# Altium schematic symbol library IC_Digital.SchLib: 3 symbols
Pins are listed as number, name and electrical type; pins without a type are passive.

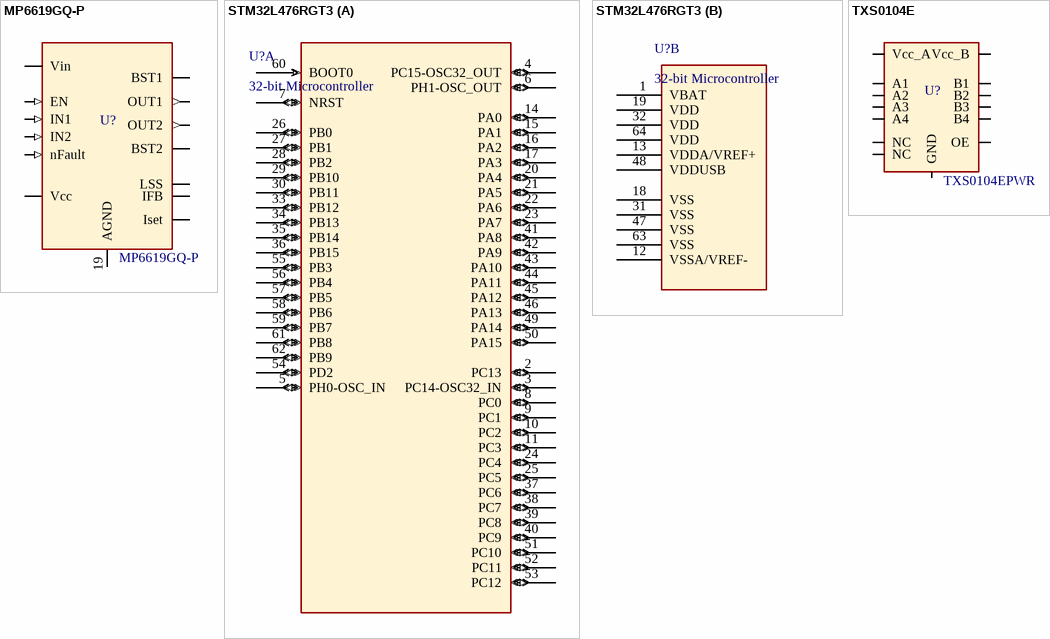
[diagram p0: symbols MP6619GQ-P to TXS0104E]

## MP6619GQ-P
designator U?  Mfr Part Num: MP6619GQ-P  (hidden comment: *)
H-Bridge Motor driver; Manufacturer: MPS; Supply Voltage: 5.4V~28V; Output Current: 5A
footprint MP6619GQ-P (19-pin, QFN-19_3x3mm)
pins: 1 IFB, 2 Vin (power), 3 OUT2 (out), 4 BST2, 5 EN (in), 6 LSS, 7 LSS, 8 LSS, 9 BST1, 10 OUT1 (out), 11 Vin (power), 13 nFault (in), 14 Vcc (power), 15 IN1 (in), 16 IN2 (in), 17 Iset, 19 AGND

## STM32L476RGT3
designator U?, comment 32-bit Microcontroller
STM32 Arm-based 32-bit Microcontroller; Mfr Part Num: STM32L476RGT3; Manufacturer: STMicroelectronics; Supply Voltage: 1.7V~3.6V; RAM Memory Size: 128kB; CPU Speed: 80MHz; Program Memory Size: 1MB
footprint LQFP64_10x10mm (10x10 mm)
part A pins: 2 PC13 (io), 3 PC14-OSC32_IN (io), 4 PC15-OSC32_OUT (io), 5 PH0-OSC_IN (io), 6 PH1-OSC_OUT (io), 7 NRST (io), 8 PC0 (io), 9 PC1 (io), 10 PC2 (io), 11 PC3 (io), 14 PA0 (io), 15 PA1 (io), 16 PA2 (io), 17 PA3 (io), 20 PA4 (io), 21 PA5 (io), 22 PA6 (io), 23 PA7 (io), 24 PC4 (io), 25 PC5 (io), 26 PB0 (io), 27 PB1 (io), 28 PB2 (io), 29 PB10 (io), 30 PB11 (io), 33 PB12 (io), 34 PB13 (io), 35 PB14 (io), 36 PB15 (io), 37 PC6 (io), 38 PC7 (io), 39 PC8 (io), 40 PC9 (io), 41 PA8 (io), 42 PA9 (io), 43 PA10 (io), 44 PA11 (io), 45 PA12 (io), 46 PA13 (io), 49 PA14 (io), 50 PA15 (io), 51 PC10 (io), 52 PC11 (io), 53 PC12 (io), 54 PD2 (io), 55 PB3 (io), 56 PB4 (io), 57 PB5 (io), 58 PB6 (io), 59 PB7 (io), 60 BOOT0 (in), 61 PB8 (io), 62 PB9 (io)
part B pins: 1 VBAT (power), 12 VSSA/VREF- (power), 13 VDDA/VREF+ (power), 18 VSS (power), 19 VDD (power), 31 VSS (power), 32 VDD (power), 47 VSS (power), 48 VDDUSB (power), 63 VSS (power), 64 VDD (power)

## TXS0104E
designator U?, comment TXS0104EPWR
Voltage Level Translator, 4 Input, 50 mA, 4.6 ns, 1.65 V to 5.5 V, TSSOP-14; Manufacturer: Texas Instruments; Supply Voltage: 1.65V~5.5V; Output Current: 50mA
footprint TSOP65P640X120-14N (TSOP, 14-Leads, Body 5.00x4.40mm, Pitch 0.65mm, IPC Medium Density)
pins: 1 Vcc_A (power), 2 A1 (power), 3 A2 (power), 4 A3 (power), 5 A4 (power), 6 NC (power), 7 GND (power), 8 OE (power), 9 NC (power), 10 B4 (power), 11 B3 (power), 12 B2 (power), 13 B1 (power), 14 Vcc_B (power)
